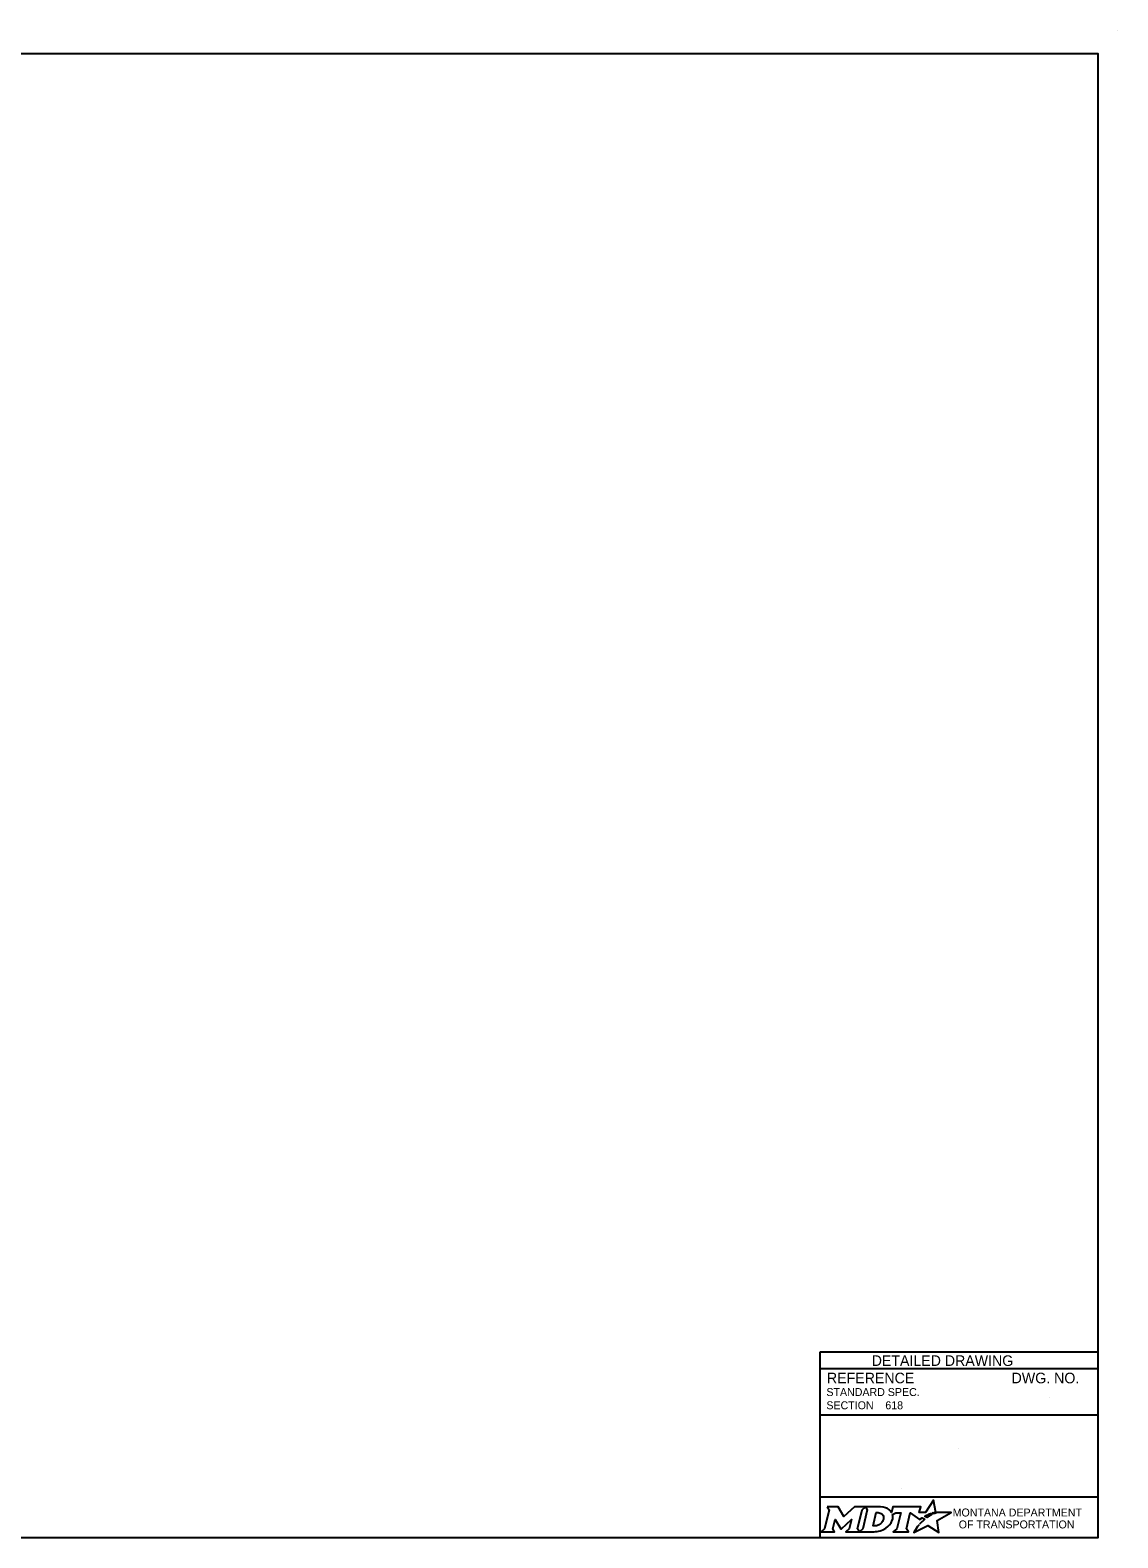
# Model space of a CAD drawing. Extents: x 49991.4 to 50021, y 49987.6 to 50011.4.
# Drawn here: x 50008.69 to 50016.9, y 49987.8 to 49999.18 of the extents above; entities that cross this region are included whole.
import ezdxf

# ---------------------------------------------------------------- set-up
doc = ezdxf.new("R2010")
doc.units = 0
for name, color, linetype in [('Default', 7, 'Continuous'), ('Level 1', 7, 'Continuous'), ('Level 2', 7, 'Continuous'), ('Level 5', 7, 'Continuous')]:
    doc.layers.add(name, color=color, linetype=linetype)

msp = doc.modelspace()

# ---------------------------------------------------------------- linework, layer by layer
at = {"layer": 'Default'}
for points in [[(50015.513, 49987.981), (50015.502, 49987.987), (50015.514, 49987.99), (50015.526, 49987.991), (50015.508, 49988.082), (50015.449, 49987.99), (50015.401, 49987.99), (50015.412, 49988.034), (50015.202, 49988.034), (50015.192, 49987.991), (50015.186, 49988)], [(50014.706, 49988.034), (50014.72, 49988.01), (50014.686, 49987.867), (50014.66, 49987.845), (50014.762, 49987.845), (50014.749, 49987.867), (50014.765, 49987.937), (50014.809, 49987.868), (50014.814, 49987.868), (50014.889, 49987.938), (50014.872, 49987.867), (50014.848, 49987.845), (50014.949, 49987.845), (50014.936, 49987.868), (50014.969, 49988.011)], [(50014.969, 49988.011), (50014.994, 49988.034), (50014.912, 49988.034), (50014.832, 49987.961), (50014.788, 49988.034), (50014.706, 49988.034)], [(50015.108, 49988.034), (50014.994, 49988.034), (50015.009, 49988.011), (50014.975, 49987.867), (50014.949, 49987.845), (50015.06, 49987.845)], [(50015.132, 49987.947), (50015.13, 49987.939), (50015.127, 49987.93), (50015.123, 49987.922), (50015.118, 49987.914), (50015.111, 49987.907), (50015.103, 49987.901), (50015.095, 49987.896), (50015.086, 49987.892), (50015.077, 49987.89), (50015.067, 49987.889), (50015.052, 49987.889), (50015.075, 49987.989), (50015.091, 49987.989), (50015.099, 49987.988), (50015.106, 49987.986), (50015.113, 49987.983), (50015.119, 49987.979), (50015.124, 49987.974), (50015.128, 49987.968), (50015.13, 49987.962), (50015.132, 49987.955), (50015.132, 49987.952), (50015.132, 49987.947)], [(50015.199, 49987.975), (50015.224, 49987.988), (50015.261, 49987.988), (50015.232, 49987.867), (50015.205, 49987.845), (50015.321, 49987.845), (50015.304, 49987.867), (50015.332, 49987.988), (50015.403, 49987.936), (50015.424, 49987.951), (50015.444, 49987.94)], [(50015.388, 49987.884), (50015.373, 49987.86), (50015.368, 49987.852), (50015.362, 49987.844), (50015.36, 49987.839), (50015.465, 49987.893), (50015.549, 49987.838), (50015.536, 49987.93), (50015.643, 49987.989), (50015.594, 49987.989), (50015.564, 49987.99), (50015.543, 49987.99), (50015.536, 49987.989), (50015.531, 49987.987), (50015.523, 49987.985), (50015.513, 49987.981)], [(50015.462, 49987.954), (50015.46, 49987.952), (50015.442, 49987.961), (50015.452, 49987.967), (50015.456, 49987.969), (50015.465, 49987.973), (50015.47, 49987.976), (50015.478, 49987.979), (50015.485, 49987.982), (50015.497, 49987.974), (50015.493, 49987.972), (50015.489, 49987.97), (50015.484, 49987.967), (50015.479, 49987.965), (50015.478, 49987.963), (50015.475, 49987.962), (50015.472, 49987.96), (50015.47, 49987.959), (50015.467, 49987.957), (50015.465, 49987.955), (50015.462, 49987.954)], [(50015.106, 49987.852), (50015.114, 49987.855), (50015.127, 49987.86), (50015.148, 49987.871)], [(50015.402, 49987.9), (50015.402, 49987.9)]]:
    msp.add_lwpolyline(points, dxfattribs=at)
for centre, radius, start, end in [((50015.087, 49987.973), 0.118, 300.9103, 339.1383), ((50015.131, 49987.955), 0.0709, 339.5329, 15.8582)]:
    msp.add_arc(centre, radius, start, end, dxfattribs=at)
for centre, major_axis, ratio, start_param, end_param in [((50015.106, 49987.986), (0.0834, -0.0037), 0.568097, 0.61298, 1.570796), ((50015.161, 49987.994), (0.0361, -0.0295), 0.469099, 1.225588, 1.570796), ((50015.433, 49987.93), (-0.0112, -0.0097), 0.021651, 3.157348, 6.283185), ((50015.06, 49987.993), (0, 0.148), 0.987302, 3.139398, 3.456847), ((50015.395, 49987.892), (-0.00694, -0.00806), 0.008222, 0, 3.137361), ((50015.412, 49987.911), (-0.0098, -0.0102), 0.016458, 3.141593, 6.279097)]:
    msp.add_ellipse(centre, major_axis=major_axis, ratio=ratio, start_param=start_param, end_param=end_param, dxfattribs=at)
at = {"layer": 'Level 1'}
for p, q in [((50016.9, 49999.176), (50016.9, 49999.176)), ((50016.386, 49988.859), (50016.386, 49988.859)), ((50015.144, 49988.799), (50015.144, 49988.799)), ((50015.7, 49988.475), (50015.7, 49988.475)), ((50015.265, 49988.169), (50015.265, 49988.169))]:
    msp.add_line(p, q, dxfattribs=at)
msp.add_lwpolyline([(49999.384, 49998.999), (50016.75, 49998.999), (50016.75, 49987.799), (49999.384, 49987.799)], close=True, dxfattribs=at)
at = {"layer": 'Level 5'}
for p, q in [((50016.75, 49989.199), (50014.65, 49989.199)), ((50014.65, 49989.199), (50014.65, 49987.799)), ((50016.75, 49989.074), (50014.65, 49989.074)), ((50016.386, 49988.859), (50016.386, 49988.859)), ((50016.75, 49988.724), (50014.65, 49988.724)), ((50015.144, 49988.799), (50015.144, 49988.799)), ((50015.7, 49988.475), (50015.7, 49988.475)), ((50016.75, 49988.106), (50014.65, 49988.106))]:
    msp.add_line(p, q, dxfattribs=at)

# ---------------------------------------------------------------- texts
at = {"layer": 'Default'}
for s, p in [('MONTANA DEPARTMENT', (50015.653, 49987.96)), ('OF TRANSPORTATION', (50015.699, 49987.87))]:
    msp.add_text(s, height=0.06, rotation=360, dxfattribs=at).set_placement(p)
at = {"layer": 'Level 2'}
msp.add_text('618', height=0.06, dxfattribs=at).set_placement((50015.145, 49988.769))
at = {"layer": 'Level 5'}
for s, height, p in [('DETAILED DRAWING', 0.0799, (50015.042, 49989.096)), ('REFERENCE', 0.08, (50014.704, 49988.965)), ('DWG. NO.', 0.08, (50016.098, 49988.965)), ('STANDARD SPEC.', 0.06, (50014.7, 49988.869)), ('SECTION', 0.06, (50014.7, 49988.769))]:
    msp.add_text(s, height=height, dxfattribs=at).set_placement(p)

doc.saveas('drawing.dxf')
